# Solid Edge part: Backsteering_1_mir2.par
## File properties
Author: KULL
Template: Iso Metric Part.par
Last saved by: KULL
Revision: 2
Application: Solid Edge
Accuracy: 0,990
Username: KULL
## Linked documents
Backsteering_1.par
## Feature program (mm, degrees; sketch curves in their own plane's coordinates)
part copy "CopiedPart_1"
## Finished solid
Body 1: solid body, 239 faces, 533 edges, 296 vertices.
  Faces by surface: cylinder 104, torus 63, plane 40, blend 27, sphere 5
  Edges by curve: circle 280, line 198, ellipse 28, intersection 26, curve on surface 1
Bounding box of the edges (mm; curved faces can reach further): 28.000 x 37.345 x 39.295, from (-5, -22.1032, -19.6474) to (23, 15.242, 19.6474).
Cylindrical faces by radius (mm): R0.2 x28, R0.8 x37, R1.3 x1, R1.8 x2, R2 x4, R3 x5, R4 x12, R5 x8, R6 x3, R8 x2, R9 x2
Toroidal faces (ring radius, tube radius in mm): R1 r0.2 x2, R1 r0.8 x2, R1.2 r0.8 x2, R1.5 r0.2 x2, R1.6 r0.2 x2, R1.7 r0.4 x1, R2.2 r0.8 x4, R2.4 r0.4 x2, R3.2 r0.2 x4, R3.2 r0.8 x2, R4.2 r0.2 x12, R4.2 r0.8 x4, R4.8 r0.2 x4, R4.8 r0.8 x4, R5.2 r0.8 x4, R5.8 r0.8 x4, R8.2 r0.2 x2, R8.8 r0.2 x2, R8.8 r0.8 x2, R9.8 r0.8 x2
Spherical faces by radius (mm): R0.8 x2, R3 x1, R4 x2
Planar faces by outward normal: +x 3, +y 5, +z 2, -x 4, -y 5, -z 2, oblique 19
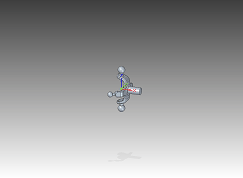
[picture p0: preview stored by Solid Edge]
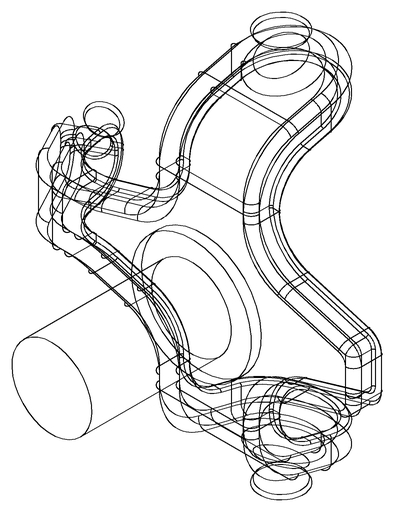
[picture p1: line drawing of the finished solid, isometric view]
